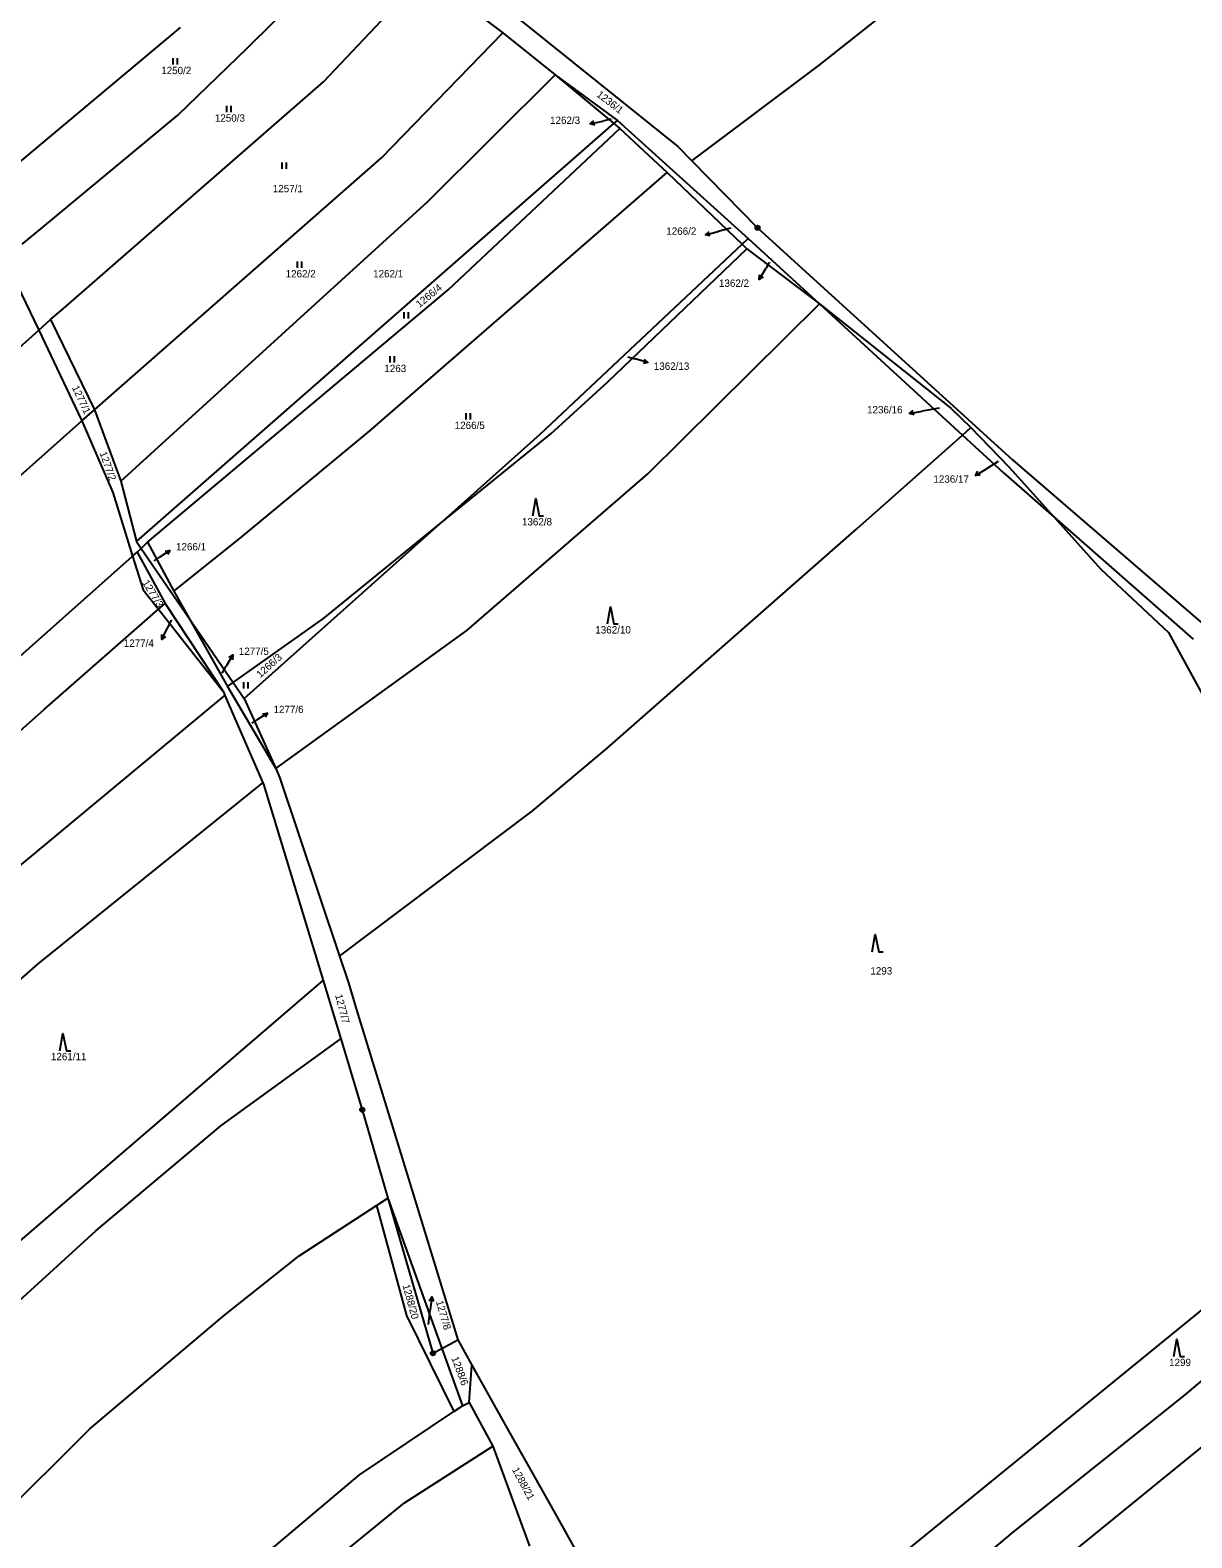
# Model space of a CAD drawing. Extents: x -763205 to -760228, y -1155311 to -1152844.
# Drawn here: x -761096.9 to -760828.3, y -1154305.4 to -1153957 of the extents above; entities that cross this region are included whole.
import ezdxf

# ---------------------------------------------------------------- set-up
doc = ezdxf.new("R2010")
doc.units = 0
for name, color, linetype in [('Vrstva 1', 7, 'Continuous'), ('Vrstva 16', 7, 'Continuous'), ('Vrstva 18', 7, 'Continuous'), ('Vrstva 24', 7, 'Continuous'), ('Vrstva 25', 7, 'Continuous'), ('Vrstva 6', 7, 'Continuous')]:
    doc.layers.add(name, color=color, linetype=linetype)

msp = doc.modelspace()

# ---------------------------------------------------------------- linework, layer by layer
at = {"layer": 'Vrstva 1'}
for p, q in [((-761029.05, -1153968.92), (-761005.6, -1153944.1)), ((-761005.6, -1153944.1), (-760987.58, -1153957.61)), ((-760989.62, -1153949.7), (-760947.14, -1153983.85)), ((-761015.58, -1153986.53), (-760987.58, -1153957.61)), ((-760987.58, -1153957.61), (-760975.49, -1153967.3)), ((-761089.17, -1154021.3), (-761029.05, -1153968.92)), ((-761004.87, -1153996.61), (-760975.49, -1153967.3)), ((-760975.49, -1153967.3), (-760961.03, -1153977.84)), ((-761072.3, -1154075.18), (-760961.89, -1153978.6)), ((-760961.89, -1153978.6), (-760961.03, -1153977.84)), ((-760961.03, -1153977.84), (-760930.81, -1154005.14)), ((-760947.14, -1153983.85), (-760943.86, -1153987.19)), ((-761082.01, -1154044.71), (-761015.58, -1153986.53)), ((-760943.86, -1153987.19), (-760928.68, -1154002.64)), ((-761075.92, -1154061.22), (-761004.87, -1153996.61)), ((-760932.24, -1154006.48), (-760930.81, -1154005.14)), ((-760930.81, -1154005.14), (-760914.33, -1154020.27)), ((-760928.68, -1154002.64), (-760869.7, -1154056.32)), ((-760978.92, -1154050.38), (-760932.24, -1154006.48)), ((-761102.76, -1154009.86), (-761094.88, -1154026.35)), ((-761092.13, -1154023.88), (-761089.17, -1154021.3)), ((-760914.33, -1154020.27), (-760881.28, -1154050.61)), ((-761094.88, -1154026.35), (-761092.13, -1154023.88)), ((-761092.13, -1154023.88), (-761082.01, -1154044.71)), ((-761094.88, -1154026.35), (-761085.73, -1154045.49)), ((-761085.73, -1154045.49), (-761084.94, -1154047.31)), ((-761082.01, -1154044.71), (-761075.92, -1154061.22)), ((-761084.94, -1154047.31), (-761077.77, -1154063.83)), ((-761002.14, -1154071.09), (-760978.92, -1154050.38)), ((-760881.28, -1154050.61), (-760871.9, -1154059.22)), ((-760869.7, -1154056.32), (-760848.01, -1154074.98)), ((-760871.9, -1154059.22), (-760860.08, -1154069.56)), ((-761077.77, -1154063.83), (-761073.17, -1154078.57)), ((-761075.92, -1154061.22), (-761072.3, -1154075.18)), ((-761047.37, -1154111.43), (-761002.14, -1154071.09)), ((-760860.08, -1154069.56), (-760827.94, -1154097.7)), ((-761072.3, -1154075.18), (-761071.21, -1154076.76)), ((-761071.21, -1154076.76), (-761060.19, -1154092.79)), ((-760848.01, -1154074.98), (-760825.8, -1154094.1)), ((-761073.17, -1154078.57), (-761070.76, -1154086.3)), ((-761070.76, -1154086.3), (-761067.2, -1154090.82)), ((-761067.2, -1154090.82), (-761052.18, -1154109.9)), ((-761060.19, -1154092.79), (-761049.9, -1154107.76)), ((-761049.9, -1154107.76), (-761047.37, -1154111.43)), ((-761052.18, -1154109.9), (-761051.83, -1154110.71)), ((-761051.83, -1154110.71), (-761043.03, -1154130.89)), ((-761047.37, -1154111.43), (-761040.07, -1154127.64)), ((-761040.07, -1154127.64), (-761039.18, -1154129.62)), ((-761039.18, -1154129.62), (-761025.32, -1154170.98)), ((-761043.03, -1154130.89), (-761042.88, -1154131.23)), ((-761042.88, -1154131.23), (-761029.13, -1154176.58)), ((-761025.32, -1154170.98), (-761023.27, -1154177.11)), ((-761122.11, -1154256.47), (-761030.68, -1154177.91)), ((-761030.68, -1154177.91), (-761029.13, -1154176.58)), ((-761029.13, -1154176.58), (-761025.04, -1154190.05)), ((-761023.27, -1154177.11), (-761021.36, -1154183.35)), ((-761021.36, -1154183.35), (-761011.15, -1154216.66)), ((-761025.04, -1154190.05), (-761020.06, -1154206.46)), ((-761020.06, -1154206.46), (-761014.12, -1154226.9)), ((-761011.15, -1154216.66), (-760997.96, -1154259.67)), ((-761014.12, -1154226.9), (-761003.72, -1154262.73)), ((-761003.72, -1154262.73), (-761001.67, -1154261.64)), ((-761001.67, -1154261.64), (-760997.96, -1154259.67)), ((-760997.96, -1154259.67), (-760994.7, -1154265.49)), ((-760994.7, -1154265.49), (-760986.61, -1154279.94)), ((-760986.61, -1154279.94), (-760975.81, -1154299.24)), ((-760975.81, -1154299.24), (-760968.63, -1154312.07))]:
    msp.add_line(p, q, dxfattribs=at)
at = {"layer": 'Vrstva 16'}
for p, q in [((-760967.394, -1153978.673), (-760964.47, -1153978)), ((-760962.6, -1153977.57), (-760964.47, -1153978)), ((-760940.691, -1154004.293), (-760937.79, -1154003.53)), ((-760934.88, -1154002.76), (-760937.79, -1154003.53)), ((-760928.331, -1154014.614), (-760926.79, -1154012.04)), ((-760925.98, -1154010.69), (-760926.79, -1154012.04)), ((-760958.7, -1154032.46), (-760956.93, -1154032.97)), ((-760954.046, -1154033.794), (-760956.93, -1154032.97)), ((-760893.556, -1154045.564), (-760890.6, -1154045.05)), ((-760886.66, -1154044.36), (-760890.6, -1154045.05)), ((-760873, -1154056.7), (-760875.73, -1154058.34)), ((-760878.303, -1154059.883), (-760875.73, -1154058.34)), ((-761064.525, -1154077.214), (-761067.02, -1154078.88)), ((-761068.19, -1154079.66), (-761067.02, -1154078.88)), ((-761066.428, -1154097.8), (-761065.1, -1154095.11)), ((-761064.23, -1154093.34), (-761065.1, -1154095.11)), ((-761050.006, -1154101.368), (-761051.5, -1154103.97)), ((-761052.44, -1154105.6), (-761051.5, -1154103.97)), ((-761045.5, -1154117.16), (-761044.48, -1154116.48)), ((-761041.985, -1154114.814), (-761044.48, -1154116.48)), ((-761003.975, -1154249.733), (-761004.35, -1154252.71)), ((-761004.78, -1154256.09), (-761004.35, -1154252.71))]:
    msp.add_line(p, q, dxfattribs=at)
for points in [[(-760966.307, -1153978.936), (-760967.394, -1153978.673), (-760966.531, -1153977.961)], [(-760939.597, -1154004.522), (-760940.691, -1154004.293), (-760939.851, -1154003.555)], [(-760927.389, -1154014.013), (-760928.331, -1154014.614), (-760928.247, -1154013.499)], [(-760954.87, -1154033.039), (-760954.046, -1154033.794), (-760955.144, -1154034)], [(-760892.485, -1154045.885), (-760893.556, -1154045.564), (-760892.656, -1154044.9)], [(-760877.188, -1154059.797), (-760878.303, -1154059.883), (-760877.702, -1154058.94)], [(-761065.634, -1154077.354), (-761064.525, -1154077.214), (-761065.079, -1154078.185)], [(-761065.537, -1154097.125), (-761066.428, -1154097.8), (-761066.434, -1154096.682)], [(-761050.938, -1154101.987), (-761050.006, -1154101.368), (-761050.071, -1154102.484)], [(-761043.094, -1154114.954), (-761041.985, -1154114.814), (-761042.539, -1154115.785)], [(-761004.596, -1154250.663), (-761003.975, -1154249.733), (-761003.604, -1154250.788)]]:
    msp.add_lwpolyline(points, dxfattribs=at)
at = {"layer": 'Vrstva 24'}
for centre, radius in [((-760928.68, -1154002.64), 0.5), ((-760928.68, -1154002.64), 0.1), ((-761020.06, -1154206.46), 0.5), ((-761020.06, -1154206.46), 0.1), ((-761003.72, -1154262.73), 0.5), ((-761003.72, -1154262.73), 0.1)]:
    msp.add_circle(centre, radius, dxfattribs=at)
at = {"layer": 'Vrstva 25'}
for p, q in [((-761063.82, -1153964.96), (-761063.82, -1153963.46)), ((-761062.82, -1153964.96), (-761062.82, -1153963.46)), ((-761051.4, -1153975.95), (-761051.4, -1153974.45)), ((-761050.4, -1153975.95), (-761050.4, -1153974.45)), ((-761038.6, -1153989.07), (-761038.6, -1153987.57)), ((-761037.6, -1153989.07), (-761037.6, -1153987.57)), ((-761035.06, -1154011.93), (-761035.06, -1154010.43)), ((-761034.06, -1154011.93), (-761034.06, -1154010.43)), ((-761010.4, -1154023.64), (-761010.4, -1154022.14)), ((-761009.4, -1154023.64), (-761009.4, -1154022.14)), ((-761013.58, -1154033.81), (-761013.58, -1154032.31)), ((-761012.58, -1154033.81), (-761012.58, -1154032.31)), ((-760996.05, -1154046.97), (-760996.05, -1154045.47)), ((-760995.05, -1154046.97), (-760995.05, -1154045.47)), ((-761047.45, -1154109.16), (-761047.45, -1154107.66)), ((-761046.45, -1154109.16), (-761046.45, -1154107.66))]:
    msp.add_line(p, q, dxfattribs=at)
for points in [[(-760980.65, -1154069.25), (-760979.95, -1154065.25), (-760979.15, -1154069.25), (-760978.15, -1154069.25)], [(-760963.38, -1154094.22), (-760962.68, -1154090.22), (-760961.88, -1154094.22), (-760960.88, -1154094.22)], [(-760902.16, -1154169.98), (-760901.46, -1154165.98), (-760900.66, -1154169.98), (-760899.66, -1154169.98)], [(-761089.96, -1154192.83), (-761089.26, -1154188.83), (-761088.46, -1154192.83), (-761087.46, -1154192.83)], [(-760832.42, -1154263.51), (-760831.72, -1154259.51), (-760830.92, -1154263.51), (-760829.92, -1154263.51)]]:
    msp.add_lwpolyline(points, dxfattribs=at)
at = {"layer": 'Vrstva 6'}
for p, q in [((-760914.47, -1153965.15), (-760868.07, -1153928.4)), ((-761046.57, -1153961.11), (-761020.15, -1153934.83)), ((-761108.53, -1153995.17), (-761062.06, -1153956.38)), ((-761062.72, -1153976.64), (-761046.57, -1153961.11)), ((-760943.86, -1153987.19), (-760914.47, -1153965.15)), ((-760975.49, -1153967.3), (-760961.89, -1153978.6)), ((-761094.38, -1154002.91), (-761062.72, -1153976.64)), ((-761000.24, -1154016.99), (-760960.54, -1153979.72)), ((-760961.89, -1153978.6), (-760960.54, -1153979.72)), ((-760960.54, -1153979.72), (-760949.57, -1153989.89)), ((-761018.31, -1154049.57), (-760949.57, -1153989.89)), ((-760949.57, -1153989.89), (-760932.24, -1154006.48)), ((-761098.68, -1154006.48), (-761094.38, -1154002.91)), ((-760963.32, -1154038.26), (-760931.12, -1154007.55)), ((-760932.24, -1154006.48), (-760931.12, -1154007.55)), ((-760931.12, -1154007.55), (-760914.33, -1154020.27)), ((-761034.7, -1154045.93), (-761000.24, -1154016.99)), ((-760954.03, -1154059.54), (-760914.33, -1154020.27)), ((-760914.33, -1154020.27), (-760883.96, -1154044.36)), ((-761254.04, -1154169.3), (-761094.88, -1154026.35)), ((-760976.49, -1154050.27), (-760963.32, -1154038.26)), ((-761084.94, -1154047.31), (-761082.01, -1154044.71)), ((-761069.71, -1154075.32), (-761034.7, -1154045.93)), ((-760883.96, -1154044.36), (-760879.38, -1154048.85)), ((-761203.04, -1154152.3), (-761084.94, -1154047.31)), ((-761048.28, -1154074.38), (-761018.31, -1154049.57)), ((-761002.14, -1154071.09), (-760976.49, -1154050.27)), ((-760881.28, -1154050.61), (-760879.38, -1154048.85)), ((-760879.38, -1154048.85), (-760870.55, -1154057.92)), ((-760905.67, -1154072.19), (-760881.28, -1154050.61)), ((-760995.86, -1154095.69), (-760954.03, -1154059.54)), ((-760870.55, -1154057.92), (-760860.08, -1154069.56)), ((-761029.06, -1154092.94), (-761002.14, -1154071.09)), ((-760860.08, -1154069.56), (-760849.29, -1154081.57)), ((-761063.65, -1154086.66), (-761048.28, -1154074.38)), ((-760963.55, -1154122.98), (-760905.67, -1154072.19)), ((-761073.17, -1154078.57), (-761072.14, -1154077.66)), ((-761072.14, -1154077.66), (-761071.21, -1154076.76)), ((-761072.14, -1154077.66), (-761065.65, -1154089.46)), ((-761071.21, -1154076.76), (-761069.71, -1154075.32)), ((-761069.71, -1154075.32), (-761063.65, -1154086.66)), ((-761123.25, -1154122.98), (-761073.17, -1154078.57)), ((-760849.29, -1154081.57), (-760833.66, -1154096.22)), ((-761063.65, -1154086.66), (-761060.19, -1154092.79)), ((-761093.54, -1154113.93), (-761067.2, -1154090.82)), ((-761067.2, -1154090.82), (-761065.65, -1154089.46)), ((-761065.65, -1154089.46), (-761052.18, -1154109.9)), ((-761060.19, -1154092.79), (-761051.22, -1154108.7)), ((-761049.9, -1154107.76), (-761029.06, -1154092.94)), ((-761040.07, -1154127.64), (-760995.86, -1154095.69)), ((-760833.66, -1154096.22), (-760820.42, -1154120.46)), ((-761051.22, -1154108.7), (-761049.9, -1154107.76)), ((-761051.22, -1154108.7), (-761040.07, -1154127.64)), ((-761109.8, -1154158.84), (-761051.83, -1154110.71)), ((-761115.69, -1154133.56), (-761093.54, -1154113.93)), ((-760980.77, -1154137.48), (-760963.55, -1154122.98)), ((-761095.03, -1154172.79), (-761043.03, -1154130.89)), ((-761025.32, -1154170.98), (-760980.77, -1154137.48)), ((-761115.27, -1154190.45), (-761095.03, -1154172.79)), ((-760829.81, -1154272.34), (-760730.96, -1154188.4)), ((-761052.78, -1154210.17), (-761025.04, -1154190.05)), ((-761081.66, -1154234.43), (-761052.78, -1154210.17)), ((-761016.77, -1154228.63), (-761014.12, -1154226.9)), ((-761014.12, -1154226.9), (-761001.67, -1154261.64)), ((-761034.64, -1154240.26), (-761016.77, -1154228.63)), ((-761016.77, -1154228.63), (-761009.82, -1154253.99)), ((-760942.66, -1154347.81), (-760796.67, -1154228.88)), ((-761153.47, -1154299.93), (-761081.66, -1154234.43)), ((-761051.92, -1154253.97), (-761034.64, -1154240.26)), ((-760828.72, -1154286.7), (-760785.34, -1154251.4)), ((-761083.04, -1154280.22), (-761051.92, -1154253.97)), ((-761009.82, -1154253.99), (-760998.89, -1154276.22)), ((-761001.67, -1154261.64), (-760996.92, -1154274.91)), ((-760995.38, -1154274.14), (-760994.7, -1154265.49)), ((-760869.56, -1154304.07), (-760829.81, -1154272.34)), ((-761020.74, -1154290.82), (-760998.89, -1154276.22)), ((-760998.89, -1154276.22), (-760996.92, -1154274.91)), ((-760996.92, -1154274.91), (-760995.38, -1154274.14)), ((-760995.38, -1154274.14), (-760989.88, -1154284.23)), ((-761161.56, -1154358.31), (-761083.04, -1154280.22)), ((-761010.32, -1154297.31), (-760989.88, -1154284.23)), ((-760989.88, -1154284.23), (-760981.38, -1154307.34)), ((-760926.95, -1154366.51), (-760828.72, -1154286.7)), ((-761041.32, -1154308.23), (-761020.74, -1154290.82)), ((-761033.07, -1154315.82), (-761010.32, -1154297.31)), ((-760934.06, -1154358.05), (-760869.56, -1154304.07))]:
    msp.add_line(p, q, dxfattribs=at)

# ---------------------------------------------------------------- texts
at = {"layer": 'Vrstva 16'}
for s, p in [('1262/3', (-760976.646, -1153978.67)), ('1266/2', (-760949.771, -1154004.29)), ('1362/2', (-760937.586, -1154016.31)), ('1362/13', (-760952.657, -1154035.49)), ('1236/16', (-760903.351, -1154045.56)), ('1236/17', (-760888.01, -1154061.58)), ('1266/1', (-761063.127, -1154077.21)), ('1277/4', (-761075.203, -1154099.5)), ('1277/5', (-761048.617, -1154101.37)), ('1277/6', (-761040.587, -1154114.81))]:
    msp.add_text(s, height=1.7, dxfattribs=at).set_placement(p)
msp.add_text('1277/8', height=1.7, rotation=286.4216, dxfattribs=at).set_placement((-761003.069, -1154250.827))
at = {"layer": 'Vrstva 18'}
for s, height, p in [('1250/2', 1.7, (-761066.547, -1153967.16)), ('1250/3', 1.7, (-761054.147, -1153978.15)), ('1262/3', 0.1, (-760962.577, -1153977.57)), ('1257/1', 1.7, (-761040.747, -1153994.45)), ('1266/2', 0.1, (-760934.857, -1154002.76)), ('1362/2', 0.1, (-760925.957, -1154010.69)), ('1262/2', 1.7, (-761037.787, -1154014.13)), ('1262/1', 1.7, (-761017.547, -1154014.13)), ('1362/13', 0.1, (-760958.677, -1154032.46)), ('1263', 1.7, (-761014.957, -1154036.01)), ('1236/16', 0.1, (-760886.637, -1154044.36)), ('1266/5', 1.7, (-760998.687, -1154049.17)), ('1236/17', 0.1, (-760872.977, -1154056.7)), ('1362/8', 1.7, (-760983.147, -1154071.45)), ('1266/1', 0.1, (-761068.167, -1154079.66)), ('1277/4', 0.1, (-761064.207, -1154093.34)), ('1362/10', 1.7, (-760966.187, -1154096.42)), ('1277/5', 0.1, (-761052.417, -1154105.6)), ('1277/6', 0.1, (-761045.477, -1154117.16)), ('1293', 1.7, (-760902.587, -1154175.23)), ('1261/11', 1.7, (-761092.047, -1154195.03)), ('1277/8', 0.1, (-761004.757, -1154256.09)), ('1299', 1.7, (-760833.517, -1154265.71))]:
    msp.add_text(s, height=height, dxfattribs=at).set_placement(p)
for s, rotation, p in [('1236/1', 322.23146, (-760966.03, -1153972.171)), ('1266/4', 39.47679, (-761006.817, -1154021.22)), ('1277/1', 294.95867, (-761087.234, -1154039.576)), ('1277/2', 289.63017, (-761080.828, -1154054.73)), ('1277/3', 302.00605, (-761071.002, -1154084.693)), ('1266/3', 41.82592, (-761043.627, -1154106.778)), ('1277/7', 284.58814, (-761026.351, -1154180.01)), ('1288/20', 285.50487, (-761010.775, -1154247.088)), ('1288/6', 290.31771, (-760999.484, -1154263.858)), ('1288/21', 298.28183, (-760985.494, -1154289.636))]:
    msp.add_text(s, height=1.7, rotation=rotation, dxfattribs=at).set_placement(p)

doc.saveas('drawing.dxf')
